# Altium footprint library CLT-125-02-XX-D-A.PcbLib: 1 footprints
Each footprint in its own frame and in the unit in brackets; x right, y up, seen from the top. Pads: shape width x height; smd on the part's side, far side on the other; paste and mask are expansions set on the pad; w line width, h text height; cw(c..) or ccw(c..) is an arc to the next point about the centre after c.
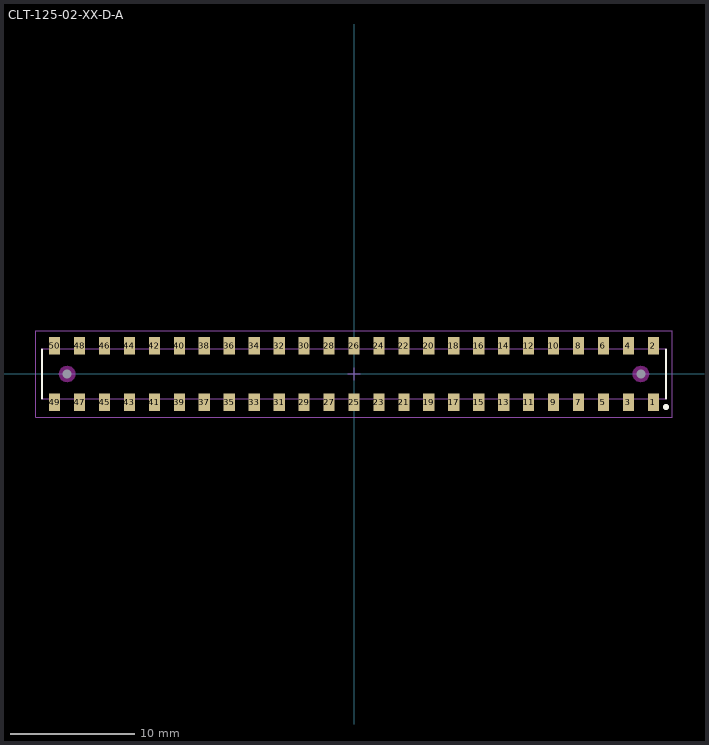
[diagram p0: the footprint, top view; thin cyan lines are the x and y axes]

## CLT-125-02-XX-D-A [mm] "2.00mm pitch, 50 pin, socket strip; low profile, w/alignment pins"
height 2.13
pads (52):
  rect 0.9x1.4 smd mask+0: 1(23.988,-2.261) 2(23.988,2.261) 3(21.989,-2.261) 4(21.989,2.261) 5(19.99,-2.261) 6(19.99,2.261) 7(17.991,-2.261) 8(17.991,2.261) 9(15.992,-2.261) 10(15.992,2.261) 11(13.993,-2.261) 12(13.993,2.261) 13(11.994,-2.261) 14(11.994,2.261) 15(9.995,-2.261) 16(9.995,2.261) 17(7.996,-2.261) 18(7.996,2.261) 19(5.997,-2.261) 20(5.997,2.261) 21(3.998,-2.261) 22(3.998,2.261) 23(1.999,-2.261) 24(1.999,2.261) 25(0,-2.261) 26(0,2.261) 27(-1.999,-2.261) 28(-1.999,2.261) 29(-3.998,-2.261) 30(-3.998,2.261) 31(-5.997,-2.261) 32(-5.997,2.261) 33(-7.996,-2.261) 34(-7.996,2.261) 35(-9.995,-2.261) 36(-9.995,2.261) 37(-11.994,-2.261) 38(-11.994,2.261) 39(-13.993,-2.261) 40(-13.993,2.261) 41(-15.992,-2.261) 42(-15.992,2.261) 43(-17.991,-2.261) 44(-17.991,2.261) 45(-19.99,-2.261) 46(-19.99,2.261) 47(-21.989,-2.261) 48(-21.989,2.261) 49(-23.988,-2.261) 50(-23.988,2.261)
  round 0.5 hole 0.7 unplated mask+0: 51(-22.988,0) 52(22.988,0)
Top Overlay:
  circle w0.25: c25,-2.65 r0.125
  lines w0.2: -25,-1.95 -25,1.95 ; 25,-1.95 25,1.95
Keep-Out Layer:
  pour cut-out: 23.644,0 23.621,0.17 23.556,0.328 23.452,0.464 23.316,0.568 23.158,0.633 22.988,0.656 22.818,0.633 22.66,0.568 22.524,0.464 22.42,0.328 22.355,0.17 22.332,0 22.355,-0.17 22.42,-0.328 22.524,-0.464 22.66,-0.568 22.818,-0.633 22.988,-0.656 23.158,-0.633 23.316,-0.568 23.452,-0.464 23.556,-0.328 23.621,-0.17
  pour cut-out: -22.332,0 -22.355,0.17 -22.42,0.328 -22.524,0.464 -22.66,0.568 -22.818,0.633 -22.988,0.656 -23.158,0.633 -23.316,0.568 -23.452,0.464 -23.556,0.328 -23.621,0.17 -23.644,0 -23.621,-0.17 -23.556,-0.328 -23.452,-0.464 -23.316,-0.568 -23.158,-0.633 -22.988,-0.656 -22.818,-0.633 -22.66,-0.568 -22.524,-0.464 -22.42,-0.328 -22.355,-0.17
Mechanical 12:
  lines w0.001: -25,-2 -25,2 25,2 25,-2 -25,-2
Mechanical 13:
  lines w0.1: -25,-2 -25,2 25,2 25,-2 -25,-2
  text ".Designator" at 0.254,0.254 h1.52
Mechanical 15:
  lines w0.05: -0.5,0 0.5,0 ; 0,-0.5 0,0.5 ; -25.495,-3.467 -25.495,3.459 25.495,3.459 25.495,-3.467 -25.495,-3.467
